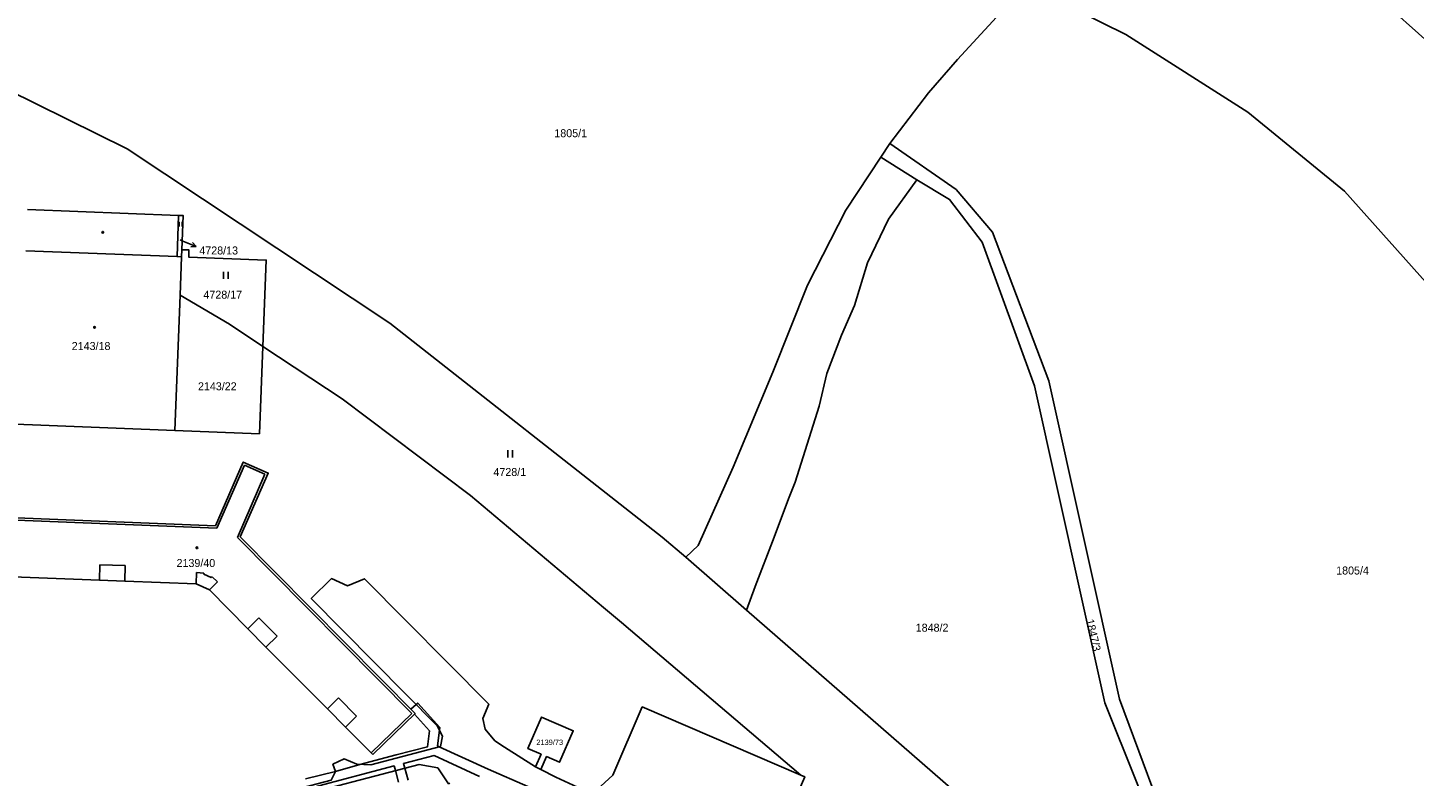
# Model space of a CAD drawing. Extents: x -756746 to -753363, y -1166406 to -1161727.
# Drawn here: x -756387.3 to -756092.8, y -1164100.9 to -1163941.9 of the extents above; entities that cross this region are included whole.
import ezdxf

# ---------------------------------------------------------------- set-up
doc = ezdxf.new("R2010")
doc.units = 0
for name, color, linetype in [('Hranice parcel', 7, 'Continuous'), ('Parcelní čísla', 7, 'Continuous'), ('Pop  PČ popisy', 7, 'Continuous'), ('Vnitřní kresba', 7, 'Continuous'), ('Věcná břemena k části', 7, 'Continuous'), ('Značky budov', 7, 'Continuous'), ('Značky kultur', 7, 'Continuous')]:
    doc.layers.add(name, color=color, linetype=linetype)

msp = doc.modelspace()

# ---------------------------------------------------------------- linework, layer by layer
at = {"layer": 'Hranice parcel'}
for p, q in [((-756206.08, -1163969.39), (-756204.15, -1163966.49)), ((-756387.38, -1163980.49), (-756355.24, -1163981.75)), ((-756354.55, -1163989.03), (-756354.61, -1163990.53)), ((-756354.93, -1163998.73), (-756354.61, -1163990.53)), ((-756356.06, -1164027.44), (-756354.93, -1163998.73)), ((-756356.06, -1164027.44), (-756393.54, -1164025.97)), ((-756252.51, -1164050.1), (-756247.53, -1164054.39)), ((-756278.31, -1164099.51), (-756279.43, -1164098.94))]:
    msp.add_line(p, q, dxfattribs=at)
for points in [[(-756126.84, -1163913.16), (-756101.04, -1163934.87), (-756076.22, -1163957.02), (-756050.4, -1163981.65), (-756036.93, -1163999.57), (-755973.83, -1164080.44), (-755962.82, -1164095.01)], [(-756204.15, -1163966.49), (-756195.99, -1163955.7), (-756189.82, -1163948.62), (-756178.19, -1163935.93), (-756174.15, -1163933.3)], [(-756174.15, -1163933.3), (-756154.03, -1163943.27), (-756128.16, -1163959.79), (-756107.63, -1163976.57), (-756082.1, -1164005.14), (-756052.14, -1164041.99), (-756028.21, -1164077.03), (-756010.47, -1164101.94), (-755994.88, -1164123.32), (-755989.52, -1164131.48)], [(-756426.02, -1163939.14), (-756410.81, -1163945.57), (-756366.17, -1163967.61)], [(-756366.17, -1163967.61), (-756310.38, -1164004.63), (-756252.51, -1164050.1)], [(-756204.15, -1163966.49), (-756190.11, -1163976.27), (-756182.34, -1163985.32), (-756170.43, -1164016.87), (-756155.36, -1164084.54), (-756143.26, -1164117.17), (-756129.48, -1164136.79), (-756106.95, -1164158.85), (-756090.98, -1164174.82)], [(-756247.53, -1164054.39), (-756244.9, -1164051.87), (-756237.42, -1164035.28), (-756229.05, -1164015.06), (-756221.68, -1163996.57), (-756213.54, -1163980.6), (-756206.08, -1163969.39)], [(-756206.08, -1163969.39), (-756198.46, -1163974.16), (-756191.49, -1163978.35), (-756184.56, -1163987.41), (-756173.45, -1164017.96), (-756158.51, -1164085.32), (-756145.23, -1164118.53), (-756130.32, -1164139.5), (-756108.46, -1164161.33), (-756093.56, -1164175.92)], [(-756354.61, -1163990.53), (-756355.56, -1163990.5), (-756355.24, -1163981.75)], [(-756355.24, -1163981.75), (-756354.26, -1163981.79), (-756354.55, -1163989.03)], [(-756354.55, -1163989.03), (-756353.05, -1163989.09), (-756353.11, -1163990.59), (-756336.62, -1163991.24), (-756337.34, -1164009.58)], [(-756337.34, -1164009.58), (-756344.47, -1164004.84), (-756354.93, -1163998.73)], [(-756337.34, -1164009.58), (-756338.07, -1164028.15), (-756356.06, -1164027.44)], [(-756264.98, -1164065.07), (-756293.22, -1164041.27), (-756320.53, -1164020.75), (-756337.34, -1164009.58)], [(-756313.99, -1164096.34), (-756305.01, -1164087.59), (-756342.17, -1164050.08), (-756336.21, -1164036.5), (-756341.51, -1164034.17), (-756347.45, -1164047.72)], [(-756347.45, -1164047.72), (-756393.31, -1164045.85), (-756393.29, -1164045.11)], [(-756247.53, -1164054.39), (-756234.65, -1164065.62), (-756160, -1164130.7), (-756156.99, -1164132.03), (-756117.62, -1164165.06)], [(-756411.52, -1164057.72), (-756411.02, -1164057.74), (-756399.64, -1164058.19), (-756394.22, -1164058.4), (-756372.09, -1164059.27), (-756366.7, -1164059.48), (-756351.53, -1164060.06), (-756348.71, -1164061.32), (-756340.54, -1164069.59), (-756336.71, -1164073.47), (-756323.63, -1164086.64), (-756319.8, -1164090.49), (-756314.34, -1164095.99), (-756313.99, -1164096.34)], [(-756279.43, -1164098.94), (-756286.01, -1164094.73), (-756288.11, -1164093.39), (-756290.16, -1164090.93), (-756290.61, -1164088.67), (-756289.39, -1164085.59), (-756315.73, -1164058.96), (-756319.35, -1164060.5), (-756322.79, -1164058.93), (-756327.09, -1164063.13), (-756300.36, -1164090.2), (-756299.18, -1164092.4), (-756299.65, -1164094.59), (-756314.4, -1164098.48), (-756317.37, -1164098.4), (-756320.09, -1164097.2), (-756322.49, -1164098.37), (-756321.91, -1164099.94), (-756322.86, -1164101.76), (-756364.17, -1164112.6), (-756363.79, -1164114.05)], [(-756223.11, -1164100.67), (-756261.2, -1164068.26), (-756264.98, -1164065.07)], [(-756223.11, -1164100.67), (-756256.77, -1164086.19), (-756263.02, -1164100.73), (-756266.38, -1164103.84), (-756270.5, -1164103.24), (-756275.14, -1164101.13), (-756278.31, -1164099.51)], [(-756278.31, -1164099.51), (-756277.1, -1164096.76), (-756274.32, -1164097.97), (-756271.44, -1164091.26), (-756278.17, -1164088.35), (-756281.05, -1164095.04), (-756278.25, -1164096.26), (-756279.43, -1164098.94)], [(-756297.61, -1164102.39), (-756297.92, -1164102.53), (-756300.21, -1164099.16), (-756304.16, -1164098.42), (-756363.79, -1164114.05)], [(-756217.29, -1164126.09), (-756225.92, -1164122.38), (-756228.59, -1164119.53), (-756228.58, -1164115.72), (-756222.26, -1164101.04), (-756223.11, -1164100.67)]]:
    msp.add_lwpolyline(points, dxfattribs=at)
at = {"layer": 'Pop  PČ popisy'}
for p, q in [((-756354.95, -1163986.95), (-756354.32, -1163987.21)), ((-756354.32, -1163987.21), (-756351.54, -1163988.33)), ((-756351.54, -1163988.33), (-756352.65, -1163988.42)), ((-756351.54, -1163988.33), (-756352.28, -1163987.5))]:
    msp.add_line(p, q, dxfattribs=at)
at = {"layer": 'Vnitřní kresba'}
for p, q in [((-756198.46, -1163974.16), (-756204.45, -1163982.56)), ((-756204.45, -1163982.56), (-756208.94, -1163991.85)), ((-756387.73, -1163989.24), (-756355.56, -1163990.5)), ((-756208.94, -1163991.85), (-756211.65, -1164000.87)), ((-756211.65, -1164000.87), (-756214.47, -1164007.2)), ((-756214.47, -1164007.2), (-756217.53, -1164015.36)), ((-756217.53, -1164015.36), (-756219.22, -1164022.28)), ((-756219.22, -1164022.28), (-756224.27, -1164038.43)), ((-756347.13, -1164048.23), (-756341.25, -1164034.83)), ((-756336.92, -1164036.74), (-756342.76, -1164050.19)), ((-756341.25, -1164034.83), (-756336.92, -1164036.74)), ((-756224.27, -1164038.43), (-756225.68, -1164041.97)), ((-756225.68, -1164041.97), (-756228.73, -1164050.12)), ((-756393.33, -1164046.37), (-756347.13, -1164048.23)), ((-756342.76, -1164050.19), (-756305.72, -1164087.58)), ((-756228.73, -1164050.12), (-756232.75, -1164060.62)), ((-756371.97, -1164055.97), (-756372.09, -1164059.27)), ((-756366.57, -1164056.16), (-756371.97, -1164055.97)), ((-756366.7, -1164059.48), (-756366.57, -1164056.16)), ((-756351.43, -1164057.65), (-756351.53, -1164060.06)), ((-756349.87, -1164057.75), (-756351.43, -1164057.65)), ((-756349.89, -1164058.02), (-756349.87, -1164057.75)), ((-756348.31, -1164058.72), (-756349.89, -1164058.02)), ((-756348.71, -1164061.32), (-756347, -1164059.62)), ((-756348.12, -1164058.52), (-756348.31, -1164058.72)), ((-756347, -1164059.62), (-756348.12, -1164058.52)), ((-756232.75, -1164060.62), (-756234.65, -1164065.62)), ((-756338.2, -1164067.27), (-756340.54, -1164069.59)), ((-756334.35, -1164071.13), (-756338.2, -1164067.27)), ((-756336.71, -1164073.47), (-756334.35, -1164071.13)), ((-756321.27, -1164084.29), (-756323.63, -1164086.64)), ((-756317.45, -1164088.15), (-756321.27, -1164084.29)), ((-756319.8, -1164090.49), (-756317.45, -1164088.15)), ((-756305.72, -1164087.58), (-756314.34, -1164095.99))]:
    msp.add_line(p, q, dxfattribs=at)
at = {"layer": 'Věcná břemena k části'}
for points in [[(-756272.67, -1164106.76), (-756289.53, -1164099.42), (-756299.9, -1164094.66), (-756300.23, -1164094.5), (-756299.84, -1164091.16), (-756299.77, -1164090.55), (-756304.45, -1164085.39), (-756304.8, -1164085.7), (-756305.9, -1164086.7), (-756305.01, -1164087.59), (-756305.17, -1164087.75), (-756301.99, -1164091.27), (-756302.38, -1164094.68), (-756309.05, -1164096.36), (-756316.77, -1164098.42), (-756321.91, -1164099.94), (-756328.27, -1164101.48)], [(-756326.56, -1164103.26), (-756309.49, -1164098.72), (-756309.21, -1164099.74), (-756308.54, -1164102.21)], [(-756306.52, -1164101.75), (-756307.22, -1164099.22), (-756307.5, -1164098.2), (-756300.96, -1164096.54), (-756291.36, -1164100.96)]]:
    msp.add_lwpolyline(points, dxfattribs=at)
at = {"layer": 'Značky budov'}
for centre in [(-756371.36, -1163985.34), (-756373.1, -1164005.54), (-756351.37, -1164052.38)]:
    msp.add_circle(centre, 0.175, dxfattribs=at)
at = {"layer": 'Značky kultur'}
for p, q in [((-756355.16, -1163984.13), (-756355.16, -1163983.12)), ((-756354.49, -1163984.13), (-756354.49, -1163983.12)), ((-756345.75, -1163995.24), (-756345.75, -1163993.74)), ((-756344.75, -1163995.24), (-756344.75, -1163993.74)), ((-756285.31, -1164033.17), (-756285.31, -1164031.67)), ((-756284.31, -1164033.17), (-756284.31, -1164031.67))]:
    msp.add_line(p, q, dxfattribs=at)

# ---------------------------------------------------------------- texts
at = {"layer": 'Parcelní čísla'}
for s, height, p in [('1805/1', 1.7, (-756275.44, -1163965.13)), ('4728/13', 1.7, (-756350.85, -1163990.05)), ('4728/17', 1.7, (-756349.98, -1163999.44)), ('2143/18', 1.7, (-756377.95, -1164010.36)), ('2143/22', 1.7, (-756351.14, -1164018.91)), ('4728/1', 1.7, (-756288.38, -1164037.13)), ('2139/40', 1.7, (-756355.69, -1164056.47)), ('1805/4', 1.7, (-756109.37, -1164058.06)), ('1848/2', 1.7, (-756198.68, -1164070.21)), ('2139/73', 1.139, (-756279.26, -1164094.29))]:
    msp.add_text(s, height=height, dxfattribs=at).set_placement(p)
msp.add_text('1847/3', height=1.7, rotation=283, dxfattribs=at).set_placement((-756162.54, -1164067.74))

doc.saveas('drawing.dxf')
